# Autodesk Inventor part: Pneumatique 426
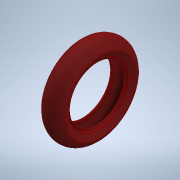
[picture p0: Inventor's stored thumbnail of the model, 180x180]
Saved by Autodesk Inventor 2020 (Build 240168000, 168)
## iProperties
Created: 2003-05
Part Number: Pneumatique 426
Material: Générique
Document SubType Name: Modeling
Designer: Bruno
Density: 1 g/cm^3
Appearance: Par défaut
Author: Bruno
Sending System: SolidWorks 2011
Last Author: frederic
Last Saved: 2012-02-22
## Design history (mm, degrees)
feature "Enlèv. mat.-Extru.1"
node "Solide1"
